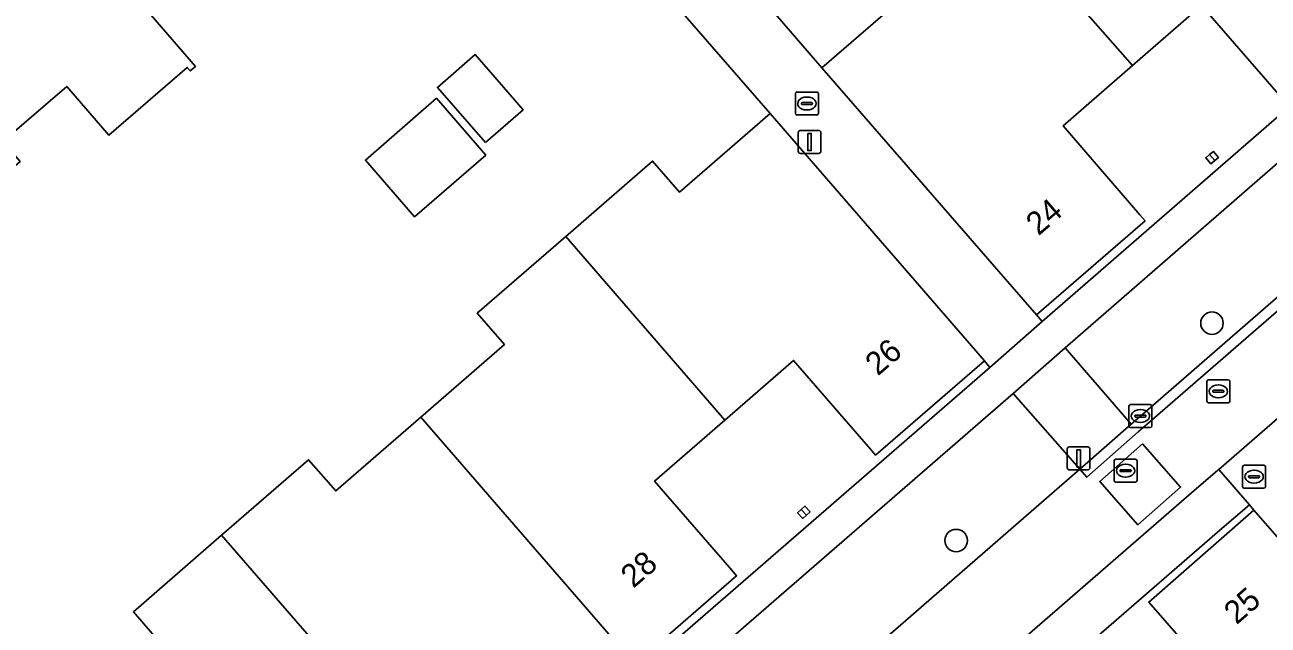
# Model space of a CAD drawing. Extents: x 155887 to 156869, y 383880 to 384678.
# Drawn here: x 156044.5 to 156098.6, y 384100.3 to 384126.4 of the extents above; entities that cross this region are included whole.
import ezdxf

# ---------------------------------------------------------------- set-up
doc = ezdxf.new("R2010")
doc.units = 0
for name, color, linetype in [('IMGEO_Boom', 7, 'Continuous'), ('IMGEO_Brandkraan', 7, 'Continuous'), ('IMGEO_Erf', 7, 'Continuous'), ('IMGEO_Kolk', 7, 'Continuous'), ('IMGEO_Lichtmast', 7, 'Continuous'), ('IMGEO_Pand', 7, 'Continuous'), ('IMGEO_Pand_nummerreeks', 7, 'Continuous'), ('IMGEO_Parkeervlak_open', 7, 'Continuous'), ('IMGEO_Rijbaan_lokaal_gesloten', 7, 'Continuous'), ('IMGEO_Rijbaan_lokaal_open', 7, 'Continuous'), ('IMGEO_Rioolput', 7, 'Continuous'), ('IMGEO_Voetpad_open', 7, 'Continuous')]:
    doc.layers.add(name, color=color, linetype=linetype)

msp = doc.modelspace()

# ---------------------------------------------------------------- linework, layer by layer
at = {"layer": 'IMGEO_Boom'}
for centre in [(156096.111, 384113.42), (156084.982, 384103.959)]:
    msp.add_circle(centre, 0.489, dxfattribs=at)
at = {"layer": 'IMGEO_Brandkraan'}
for p, q in [((156097.517, 384107.239), (156098.369, 384107.239)), ((156097.442, 384106.313), (156097.442, 384107.165)), ((156097.701, 384106.733), (156097.701, 384106.745)), ((156098.139, 384106.696), (156097.741, 384106.696)), ((156097.744, 384106.782), (156098.142, 384106.782)), ((156097.93, 384107.019), (156097.955, 384107.019)), ((156098.185, 384106.745), (156098.185, 384106.733)), ((156098.443, 384107.165), (156098.443, 384106.313)), ((156098.369, 384106.239), (156097.517, 384106.239)), ((156097.953, 384106.459), (156097.928, 384106.459))]:
    msp.add_line(p, q, dxfattribs=at)
for points in [[(156097.517, 384107.239), (156098.369, 384107.239)], [(156097.442, 384106.313), (156097.442, 384107.165)], [(156098.443, 384107.165), (156098.443, 384106.313)], [(156098.369, 384106.239), (156097.517, 384106.239)]]:
    msp.add_lwpolyline(points, dxfattribs=at)
for centre, radius, start, end in [((156097.519, 384107.163), 0.0765, 91.552, 178.448), ((156097.519, 384107.163), 0.0765, 91.552, 178.448), ((156098.367, 384107.163), 0.0765, 1.552, 88.448), ((156098.367, 384107.163), 0.0765, 1.552, 88.448), ((156097.741, 384106.742), 0.0403, 85.8775, 175.7526), ((156097.738, 384106.732), 0.0366, 178.938, 274.7102), ((156098.142, 384106.739), 0.043, 264.8664, 352.4533), ((156098.146, 384106.744), 0.0386, 1.7309, 96.639), ((156097.519, 384106.315), 0.0765, 181.552, 268.448), ((156097.519, 384106.315), 0.0765, 181.552, 268.448), ((156098.367, 384106.315), 0.0765, 271.552, 358.448), ((156098.367, 384106.315), 0.0765, 271.552, 358.448)]:
    msp.add_arc(centre, radius, start, end, dxfattribs=at)
for centre, major_axis, ratio, start_param, end_param in [((156097.929, 384106.739), (-0.387, 0.002), 0.722429, 4.712389, 7.853982), ((156097.954, 384106.739), (-0.39, 0.002), 0.717154, 1.570796, 4.712389)]:
    msp.add_ellipse(centre, major_axis=major_axis, ratio=ratio, start_param=start_param, end_param=end_param, dxfattribs=at)
at = {"layer": 'IMGEO_Erf'}
for points in [[(156146.041, 384229.773), (156083.269, 384175.304), (156055.794, 384151.364), (156065.559, 384140.115), (156072.254, 384132.504), (156079.139, 384124.535), (156083.063, 384127.942), (156081.884, 384129.301), (156085.659, 384132.579), (156089.506, 384135.919), (156090.686, 384134.56), (156094.356, 384137.746), (156098.014, 384140.923), (156096.835, 384142.281), (156100.645, 384145.59)], [(156099.008, 384123.386), (156095.658, 384127.239), (156092.657, 384124.628), (156089.634, 384121.998), (156092.974, 384118.136), (156093.199, 384117.875), (156088.469, 384113.785), (156088.717, 384113.496), (156178.911, 384191.881)], [(156050.36, 384099.499), (156049.179, 384100.858), (156053.02, 384104.194), (156056.805, 384107.48), (156057.985, 384106.121), (156061.68, 384109.33), (156065.323, 384112.494), (156064.143, 384113.853), (156067.993, 384117.196), (156071.768, 384120.475), (156072.948, 384119.116), (156076.889, 384122.539), (156069.973, 384130.498)], [(156000, 384036.51), (156086.442, 384111.494), (156086.213, 384111.78), (156081.474, 384107.68), (156081.257, 384107.931), (156077.908, 384111.802), (156074.91, 384109.195), (156071.855, 384106.538), (156075.212, 384102.673), (156075.429, 384102.423), (156071.003, 384098.579)], [(156096.944, 384097.182), (156093.357, 384101.285), (156097.934, 384105.287), (156097.741, 384105.518), (156096.561, 384104.495), (156064.539, 384076.733)]]:
    msp.add_lwpolyline(points, dxfattribs=at)
for points in [[(156048.113, 384121.597), (156046.28, 384123.72), (156043.505, 384121.324), (156044.251, 384120.459), (156040.149, 384116.917), (156036.639, 384120.981), (156037.473, 384121.726), (156033.379, 384126.47), (156035.041, 384127.914), (156034.303, 384128.763), (156037.204, 384131.284), (156037.93, 384130.448), (156039.612, 384131.91), (156043.311, 384127.654), (156046.703, 384130.589), (156051.884, 384124.589), (156051.656, 384124.392), (156051.525, 384124.544)], [(156064.496, 384121.274), (156062.41, 384123.675), (156064.054, 384125.103), (156066.14, 384122.702)], [(156064.509, 384120.736), (156061.416, 384118.049), (156059.274, 384120.515), (156062.367, 384123.202)], [(156096.172, 384120.894), (156096.393, 384120.629), (156096.228, 384120.492), (156096.064, 384120.355), (156095.843, 384120.62), (156096.008, 384120.758)], [(156078.081, 384105.171), (156078.237, 384105.314), (156078.398, 384105.461), (156078.621, 384105.216), (156078.464, 384105.072), (156078.304, 384104.926)]]:
    msp.add_lwpolyline(points, close=True, dxfattribs=at)
at = {"layer": 'IMGEO_Kolk'}
for p, q in [((156077.985, 384122.551), (156077.985, 384123.403)), ((156078.06, 384123.477), (156078.912, 384123.477)), ((156078.986, 384123.403), (156078.986, 384122.551)), ((156078.244, 384122.971), (156078.244, 384122.983)), ((156078.682, 384122.934), (156078.284, 384122.934)), ((156078.287, 384123.02), (156078.685, 384123.02)), ((156078.473, 384123.257), (156078.498, 384123.257)), ((156078.728, 384122.983), (156078.728, 384122.971)), ((156078.912, 384122.477), (156078.06, 384122.477)), ((156078.496, 384122.697), (156078.471, 384122.697)), ((156092.571, 384109.878), (156093.423, 384109.878)), ((156092.496, 384108.952), (156092.496, 384109.804)), ((156092.755, 384109.372), (156092.755, 384109.384)), ((156093.193, 384109.335), (156092.795, 384109.335)), ((156092.798, 384109.421), (156093.196, 384109.421)), ((156092.984, 384109.658), (156093.009, 384109.658)), ((156093.239, 384109.384), (156093.239, 384109.372)), ((156093.497, 384109.804), (156093.497, 384108.952)), ((156093.423, 384108.878), (156092.571, 384108.878)), ((156093.007, 384109.098), (156092.982, 384109.098))]:
    msp.add_line(p, q, dxfattribs=at)
for points in [[(156077.985, 384122.551), (156077.985, 384123.403)], [(156078.06, 384123.477), (156078.912, 384123.477)], [(156078.986, 384123.403), (156078.986, 384122.551)], [(156078.912, 384122.477), (156078.06, 384122.477)], [(156092.571, 384109.878), (156093.423, 384109.878)], [(156092.496, 384108.952), (156092.496, 384109.804)], [(156093.497, 384109.804), (156093.497, 384108.952)], [(156093.423, 384108.878), (156092.571, 384108.878)]]:
    msp.add_lwpolyline(points, dxfattribs=at)
for centre, radius, start, end in [((156078.062, 384123.401), 0.0765, 91.552, 178.448), ((156078.062, 384123.401), 0.0765, 91.552, 178.448), ((156078.91, 384123.401), 0.0765, 1.552, 88.448), ((156078.91, 384123.401), 0.0765, 1.552, 88.448), ((156078.284, 384122.98), 0.0403, 85.8775, 175.7526), ((156078.281, 384122.97), 0.0366, 178.938, 274.7102), ((156078.685, 384122.977), 0.043, 264.8664, 352.4533), ((156078.689, 384122.982), 0.0386, 1.7309, 96.639), ((156078.062, 384122.553), 0.0765, 181.552, 268.448), ((156078.062, 384122.553), 0.0765, 181.552, 268.448), ((156078.91, 384122.553), 0.0765, 271.552, 358.448), ((156078.91, 384122.553), 0.0765, 271.552, 358.448), ((156092.573, 384109.802), 0.0765, 91.552, 178.448), ((156092.573, 384109.802), 0.0765, 91.552, 178.448), ((156093.421, 384109.802), 0.0765, 1.552, 88.448), ((156093.421, 384109.802), 0.0765, 1.552, 88.448), ((156092.795, 384109.381), 0.0403, 85.8775, 175.7526), ((156092.792, 384109.371), 0.0366, 178.938, 274.7102), ((156093.196, 384109.378), 0.043, 264.8664, 352.4533), ((156093.2, 384109.383), 0.0386, 1.7309, 96.639), ((156092.573, 384108.954), 0.0765, 181.552, 268.448), ((156092.573, 384108.954), 0.0765, 181.552, 268.448), ((156093.421, 384108.954), 0.0765, 271.552, 358.448), ((156093.421, 384108.954), 0.0765, 271.552, 358.448)]:
    msp.add_arc(centre, radius, start, end, dxfattribs=at)
for centre, major_axis, ratio, start_param, end_param in [((156078.472, 384122.977), (-0.387, 0.002), 0.722429, 4.712389, 7.853982), ((156078.497, 384122.977), (-0.39, 0.002), 0.717154, 1.570796, 4.712389), ((156092.983, 384109.378), (-0.387, 0.002), 0.722429, 4.712389, 7.853982), ((156093.008, 384109.378), (-0.39, 0.002), 0.717154, 1.570796, 4.712389)]:
    msp.add_ellipse(centre, major_axis=major_axis, ratio=ratio, start_param=start_param, end_param=end_param, dxfattribs=at)
at = {"layer": 'IMGEO_Lichtmast'}
for p, q in [((156078.205, 384121.803), (156078.995, 384121.803)), ((156078.995, 384121.803), (156078.205, 384121.803)), ((156078.105, 384120.903), (156078.105, 384121.703)), ((156078.105, 384121.703), (156078.105, 384120.903)), ((156079.095, 384121.703), (156079.095, 384120.903)), ((156079.095, 384120.903), (156079.095, 384121.703)), ((156078.995, 384120.803), (156078.205, 384120.803)), ((156078.205, 384120.803), (156078.995, 384120.803)), ((156089.813, 384107.135), (156089.813, 384107.935)), ((156089.813, 384107.935), (156089.813, 384107.135)), ((156089.913, 384108.035), (156090.703, 384108.035)), ((156090.703, 384108.035), (156089.913, 384108.035)), ((156090.803, 384107.935), (156090.803, 384107.135)), ((156090.803, 384107.135), (156090.803, 384107.935)), ((156090.703, 384107.035), (156089.913, 384107.035)), ((156089.913, 384107.035), (156090.703, 384107.035))]:
    msp.add_line(p, q, dxfattribs=at)
for points in [[(156078.525, 384121.678), (156078.675, 384121.678), (156078.675, 384120.928), (156078.525, 384120.928), (156078.525, 384121.678)], [(156090.233, 384107.91), (156090.383, 384107.91), (156090.383, 384107.16), (156090.233, 384107.16), (156090.233, 384107.91)]]:
    msp.add_lwpolyline(points, dxfattribs=at)
for centre, start, end in [((156078.205, 384121.703), 90, 180), ((156078.205, 384121.703), 90, 180), ((156078.995, 384121.703), 0, 90), ((156078.995, 384121.703), 360, 90), ((156078.205, 384120.903), 180, 270), ((156078.205, 384120.903), 180, 270), ((156078.995, 384120.903), 270, 0), ((156078.995, 384120.903), 270, 0), ((156089.913, 384107.935), 90, 180), ((156089.913, 384107.935), 90, 180), ((156090.703, 384107.935), 0, 90), ((156090.703, 384107.935), 360, 90), ((156089.913, 384107.135), 180, 270), ((156089.913, 384107.135), 180, 270), ((156090.703, 384107.135), 270, 0), ((156090.703, 384107.135), 270, 0)]:
    msp.add_arc(centre, 0.1, start, end, dxfattribs=at)
at = {"layer": 'IMGEO_Pand'}
for points in [[(156103.681, 384126.992), (156094.356, 384137.746), (156090.686, 384134.56), (156089.506, 384135.919), (156085.659, 384132.579), (156092.657, 384124.628), (156095.658, 384127.239), (156099.008, 384123.386), (156099.234, 384123.126)], [(156092.657, 384124.628), (156085.659, 384132.579), (156081.884, 384129.301), (156083.063, 384127.942), (156079.139, 384124.535), (156088.469, 384113.785), (156093.199, 384117.875), (156092.974, 384118.136), (156089.634, 384121.998)], [(156040.149, 384116.917), (156044.251, 384120.459), (156043.505, 384121.324), (156046.28, 384123.72), (156048.113, 384121.597), (156051.525, 384124.544), (156051.656, 384124.392), (156051.884, 384124.589), (156046.703, 384130.589), (156043.311, 384127.654), (156039.612, 384131.91), (156037.93, 384130.448), (156037.204, 384131.284), (156034.303, 384128.763), (156035.041, 384127.914), (156033.379, 384126.47), (156037.473, 384121.726), (156036.639, 384120.981)], [(156064.496, 384121.274), (156066.14, 384122.702), (156064.054, 384125.103), (156062.41, 384123.675)], [(156064.509, 384120.736), (156062.367, 384123.202), (156059.274, 384120.515), (156061.416, 384118.049)], [(156067.993, 384117.196), (156074.91, 384109.195), (156077.908, 384111.802), (156081.257, 384107.931), (156081.474, 384107.68), (156086.213, 384111.78), (156076.889, 384122.539), (156072.948, 384119.116), (156071.768, 384120.475)], [(156096.228, 384120.492), (156096.008, 384120.758), (156095.843, 384120.62), (156096.064, 384120.355)], [(156096.008, 384120.758), (156096.228, 384120.492), (156096.393, 384120.629), (156096.172, 384120.894)], [(156071.003, 384098.579), (156075.429, 384102.423), (156075.212, 384102.673), (156071.855, 384106.538), (156074.91, 384109.195), (156067.993, 384117.196), (156064.143, 384113.853), (156065.323, 384112.494), (156061.68, 384109.33)], [(156071.003, 384098.579), (156061.68, 384109.33), (156057.985, 384106.121), (156056.805, 384107.48), (156053.02, 384104.194), (156059.957, 384096.196), (156062.974, 384098.825), (156066.331, 384094.96), (156066.548, 384094.71)], [(156078.464, 384105.072), (156078.237, 384105.314), (156078.081, 384105.171), (156078.304, 384104.926)], [(156078.237, 384105.314), (156078.464, 384105.072), (156078.621, 384105.216), (156078.398, 384105.461)], [(156094.373, 384094.959), (156096.458, 384092.552), (156098.435, 384094.265), (156101.004, 384091.308), (156101.141, 384091.427), (156106.198, 384095.821), (156097.934, 384105.287), (156093.357, 384101.285), (156096.944, 384097.182), (156096.73, 384096.997)], [(156056.046, 384085.575), (156060.491, 384089.432), (156060.274, 384089.683), (156056.92, 384093.549), (156059.957, 384096.196), (156053.02, 384104.194), (156049.179, 384100.858), (156050.36, 384099.499), (156046.712, 384096.331)]]:
    msp.add_lwpolyline(points, close=True, dxfattribs=at)
at = {"layer": 'IMGEO_Parkeervlak_open'}
for points in [[(156089.722, 384112.346), (156092.601, 384109.03), (156092.996, 384109.38), (156107.334, 384121.829), (156104.435, 384125.134)], [(156090.359, 384107.06), (156087.459, 384110.362), (156070.574, 384095.715), (156073.437, 384092.345)]]:
    msp.add_lwpolyline(points, close=True, dxfattribs=at)
at = {"layer": 'IMGEO_Rijbaan_lokaal_gesloten'}
for points in [[(156185.633, 384184.294), (156182.874, 384187.645), (156181.472, 384186.221), (156180.056, 384184.813), (156178.624, 384183.419), (156177.178, 384182.041), (156175.717, 384180.678), (156174.242, 384179.33), (156140.299, 384149.84), (156093.299, 384109.034), (156092.905, 384108.685), (156090.661, 384106.714), (156090.359, 384107.06), (156073.437, 384092.345)], [(156000, 384023.453), (156000.779, 384024.065), (156095.22, 384106.032), (156096.361, 384107.023), (156096.403, 384107.059), (156182.818, 384182.155)]]:
    msp.add_lwpolyline(points, dxfattribs=at)
msp.add_lwpolyline([(156094.748, 384106.282), (156092.891, 384104.641), (156091.226, 384106.526), (156093.083, 384108.166)], close=True, dxfattribs=at)
at = {"layer": 'IMGEO_Rijbaan_lokaal_open'}
msp.add_lwpolyline([(156107.334, 384121.829), (156092.996, 384109.38), (156092.601, 384109.03), (156090.359, 384107.06), (156090.661, 384106.714), (156092.905, 384108.685), (156093.299, 384109.034), (156140.299, 384149.84)], dxfattribs=at)
msp.add_lwpolyline([(156092.891, 384104.641), (156094.748, 384106.282), (156093.083, 384108.166), (156091.226, 384106.526)], close=True, dxfattribs=at)
at = {"layer": 'IMGEO_Rioolput'}
for p, q in [((156095.887, 384110.028), (156095.887, 384110.88)), ((156095.962, 384110.954), (156096.814, 384110.954)), ((156096.146, 384110.448), (156096.146, 384110.46)), ((156096.189, 384110.497), (156096.587, 384110.497)), ((156096.375, 384110.734), (156096.4, 384110.734)), ((156096.63, 384110.46), (156096.63, 384110.448)), ((156096.888, 384110.88), (156096.888, 384110.028)), ((156096.814, 384109.954), (156095.962, 384109.954)), ((156096.584, 384110.411), (156096.186, 384110.411)), ((156096.398, 384110.174), (156096.373, 384110.174)), ((156091.851, 384106.576), (156091.851, 384107.428)), ((156091.926, 384107.502), (156092.778, 384107.502)), ((156092.339, 384107.282), (156092.364, 384107.282)), ((156092.852, 384107.428), (156092.852, 384106.576)), ((156092.11, 384106.996), (156092.11, 384107.008)), ((156092.548, 384106.959), (156092.15, 384106.959)), ((156092.153, 384107.045), (156092.551, 384107.045)), ((156092.362, 384106.722), (156092.337, 384106.722)), ((156092.594, 384107.008), (156092.594, 384106.996)), ((156092.778, 384106.502), (156091.926, 384106.502))]:
    msp.add_line(p, q, dxfattribs=at)
for points in [[(156095.887, 384110.028), (156095.887, 384110.88)], [(156095.962, 384110.954), (156096.814, 384110.954)], [(156096.888, 384110.88), (156096.888, 384110.028)], [(156096.814, 384109.954), (156095.962, 384109.954)], [(156091.851, 384106.576), (156091.851, 384107.428)], [(156091.926, 384107.502), (156092.778, 384107.502)], [(156092.852, 384107.428), (156092.852, 384106.576)], [(156092.778, 384106.502), (156091.926, 384106.502)]]:
    msp.add_lwpolyline(points, dxfattribs=at)
for centre, radius, start, end in [((156095.964, 384110.878), 0.0765, 91.552, 178.448), ((156095.964, 384110.878), 0.0765, 91.552, 178.448), ((156096.186, 384110.457), 0.0403, 85.8775, 175.7526), ((156096.183, 384110.447), 0.0366, 178.938, 274.7102), ((156096.587, 384110.454), 0.043, 264.8664, 352.4533), ((156096.591, 384110.459), 0.0386, 1.7309, 96.639), ((156096.812, 384110.878), 0.0765, 1.552, 88.448), ((156096.812, 384110.878), 0.0765, 1.552, 88.448), ((156095.964, 384110.03), 0.0765, 181.552, 268.448), ((156095.964, 384110.03), 0.0765, 181.552, 268.448), ((156096.812, 384110.03), 0.0765, 271.552, 358.448), ((156096.812, 384110.03), 0.0765, 271.552, 358.448), ((156091.928, 384107.426), 0.0765, 91.552, 178.448), ((156091.928, 384107.426), 0.0765, 91.552, 178.448), ((156092.776, 384107.426), 0.0765, 1.552, 88.448), ((156092.776, 384107.426), 0.0765, 1.552, 88.448), ((156092.15, 384107.005), 0.0403, 85.8775, 175.7526), ((156092.147, 384106.995), 0.0366, 178.938, 274.7102), ((156092.551, 384107.002), 0.043, 264.8664, 352.4533), ((156092.555, 384107.007), 0.0386, 1.7309, 96.639), ((156091.928, 384106.578), 0.0765, 181.552, 268.448), ((156091.928, 384106.578), 0.0765, 181.552, 268.448), ((156092.776, 384106.578), 0.0765, 271.552, 358.448), ((156092.776, 384106.578), 0.0765, 271.552, 358.448)]:
    msp.add_arc(centre, radius, start, end, dxfattribs=at)
for centre, major_axis, ratio, start_param, end_param in [((156096.374, 384110.454), (-0.387, 0.002), 0.722429, 4.712389, 7.853982), ((156096.399, 384110.454), (-0.39, 0.002), 0.717154, 1.570796, 4.712389), ((156092.338, 384107.002), (-0.387, 0.002), 0.722429, 4.712389, 7.853982), ((156092.363, 384107.002), (-0.39, 0.002), 0.717154, 1.570796, 4.712389)]:
    msp.add_ellipse(centre, major_axis=major_axis, ratio=ratio, start_param=start_param, end_param=end_param, dxfattribs=at)
at = {"layer": 'IMGEO_Voetpad_open'}
for points in [[(156070.574, 384095.715), (156087.459, 384110.362), (156089.722, 384112.346), (156104.435, 384125.134), (156105.279, 384125.867), (156119.306, 384138.058), (156120.154, 384138.795), (156134.547, 384151.304), (156137.427, 384153.807), (156149.311, 384164.136), (156150.476, 384165.148), (156163.776, 384176.707), (156164.856, 384177.647), (156179.904, 384190.725), (156178.911, 384191.881), (156088.717, 384113.496), (156086.442, 384111.494), (156000, 384036.51)], [(156182.818, 384182.155), (156096.403, 384107.059), (156097.741, 384105.518), (156097.934, 384105.287), (156106.198, 384095.821), (156112.601, 384088.452), (156115.028, 384085.659), (156116.761, 384083.662), (156121.154, 384078.608), (156130.296, 384068.003), (156130.502, 384067.788), (156131.822, 384066.268), (156220.134, 384142.954)], [(156000, 384020.578), (156001.423, 384021.932), (156025.456, 384042.703), (156037.26, 384052.977), (156041.863, 384057.029), (156046.015, 384060.684), (156046.361, 384060.988), (156049.308, 384063.528), (156064.539, 384076.733), (156096.561, 384104.495), (156097.741, 384105.518), (156096.403, 384107.059), (156096.361, 384107.023), (156095.22, 384106.032), (156000.779, 384024.065), (156000, 384023.453)]]:
    msp.add_lwpolyline(points, dxfattribs=at)
for points in [[(156072.254, 384132.504), (156065.559, 384140.115), (156055.794, 384151.364), (156053.505, 384149.41), (156060.939, 384140.901), (156066.498, 384134.486), (156069.973, 384130.498), (156076.889, 384122.539), (156086.213, 384111.78), (156086.442, 384111.494), (156088.717, 384113.496), (156088.469, 384113.785), (156079.139, 384124.535)], [(156089.722, 384112.346), (156087.459, 384110.362), (156090.359, 384107.06), (156092.601, 384109.03)]]:
    msp.add_lwpolyline(points, close=True, dxfattribs=at)

# ---------------------------------------------------------------- texts
at = {"layer": 'IMGEO_Pand_nummerreeks'}
for s, rotation, p in [('24', 40.8498, (156088.561, 384117.196)), ('26', 40.8651, (156081.57, 384111.095)), ('28', 40.9738, (156070.934, 384101.858)), ('25', 41.1655, (156097.182, 384100.273))]:
    msp.add_text(s, height=1, rotation=rotation, dxfattribs=at).set_placement(p)

doc.saveas('drawing.dxf')
